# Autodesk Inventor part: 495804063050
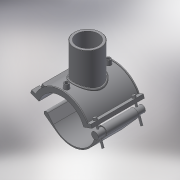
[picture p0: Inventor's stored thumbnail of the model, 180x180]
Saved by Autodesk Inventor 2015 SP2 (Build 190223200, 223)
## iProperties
Created: 2017-07
Part Number: 495804063050
Material: Generic
Description: PLASSON BRANCH SADDLE 63-50
Document SubType Name: Modeling
Designer: KIM
Density: 1 g/cm^3
Appearance: Default
Author: KIM
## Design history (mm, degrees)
derived "495804.ipt"
feature "Solid1::495804.ipt"
feature "Solid2::495804.ipt"
tag "TaggingFeature1"
body "Solid1"
body "Solid2"
other parameters: "d0" = 63, "d3" = 15.75, "d4" = 118, "d5" = 0, "d6" = 0.1, "d8" = 0, "d19" = 6, "d20" = 6, "d21" = 70.8, "d23" = 0, "d24" = 35.4, "d26" = 0, "d27" = 3, "d28" = 3, "d29" = 3, "d30" = 21, "d31" = 6, "d32" = 0, "d33" = 0, "d34" = 0.6, "d40" = 44.2, "d41" = 55, "d43" = 0, "d45" = 0, "d47" = 135.5, "d50" = 0, "d70" = 15, "d72" = 0, "d73" = 6, "d75" = 5, "d76" = 0, "d77" = 3.15, "d78" = 61.5, "d79" = 15, "d80" = 47.2, "d82" = 5 deg, "d84" = 4, "d85" = 14, "d86" = 0, "d87" = 3, "d88" = 0, "d89" = 1, "d90" = 1, "d91" = 94.4, "d92" = 0, "d93" = 0.5, "d94" = 33.15789, "d96" = 86.7, "d97" = 2.36, "d98" = 0, "d102" = 1.5, "d105" = 0, "d109" = -31, "d117" = 0.5, "d120" = 140 deg, "d121" = 24.228, "d122" = 20 deg, "d124" = 51, "d126" = 0, "d143" = 66.15, "d150" = 11.34, "d159" = 4.4, "d161" = 1.575, "d162" = 70.8, "d163" = 0, "d167" = 12.6, "d168" = 38.63636, "d173" = 1, "d175" = 31.5, "d176" = 20 deg, "d177" = 4.41, "d178" = 22, "d180" = 0, "d185" = 38.35, "d186" = 38.35, "d187" = 42.5, "d188" = 6.6, "d189" = 4.41, "d190" = 0, "d191" = 63.75, "d200" = 11, "d202" = 0, "d216" = 106.2, "d217" = 0, "d221" = 43.66, "d222" = 4.41, "d223" = 2.646, "d224" = 31.5, "d225" = 2.646, "d227" = 9.072, "d230" = 39.06, "d236" = 20 deg, "d237" = 49.5, "d238" = 20 deg, "d239" = 4.41, "d_" = 63, "H_" = 93, "L_" = 118, "d_t" = 6, "H_1" = 82, "d1" = 85, "d148" = 1.575, "d160" = 1.575
